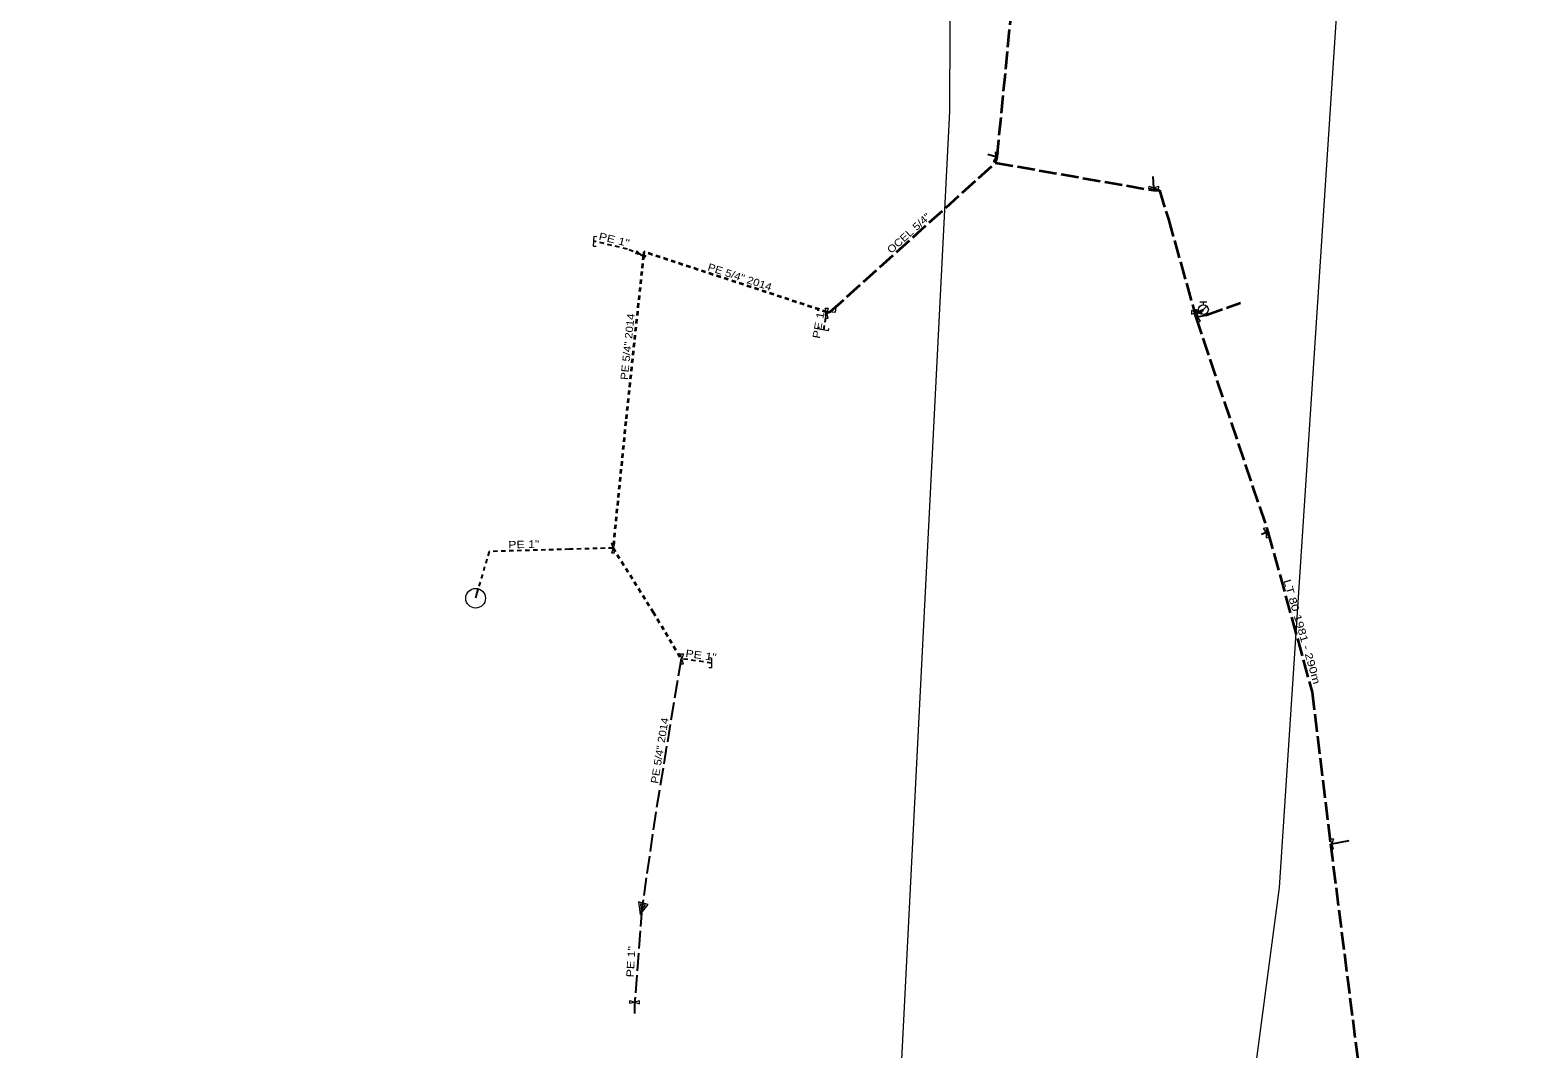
# Model space of a CAD drawing. Extents: x -616592 to -615844, y -1088988 to -1088174.
# Drawn here: x -616410.7 to -616257.7, y -1088838.7 to -1088735.2 of the extents above; entities that cross this region are included whole.
import ezdxf
from ezdxf.enums import TextEntityAlignment as Align

# ---------------------------------------------------------------- set-up
doc = ezdxf.new("R2010")
doc.units = 0
doc.header["$LTSCALE"] = 0.3
doc.linetypes.add('LONG_DASHED', pattern=[7.5, 6, -1.5])
doc.linetypes.add('SHORT_DASHED', pattern=[2.7, 1.5, -1.2])
for name, color, linetype, lineweight in [('1', 7, 'Continuous', 13), ('10', 7, 'Continuous', 13), ('35', 7, 'LONG_DASHED', 35), ('36', 7, 'SHORT_DASHED', 35), ('50', 7, 'LONG_DASHED', 25), ('51', 7, 'SHORT_DASHED', 25)]:
    doc.layers.add(name, color=color, linetype=linetype, lineweight=lineweight)
doc.layers.add('16', color=7, linetype='Continuous')
doc.layers.add('19', color=7, linetype='Continuous')

msp = doc.modelspace()

# ---------------------------------------------------------------- linework, layer by layer
at = {"layer": '1'}
msp.add_lwpolyline([(-616257.711, -1088587.328), (-616274.902, -1088683.788), (-616283.975, -1088822.271), (-616298.779, -1088934.012), (-616386.643, -1088972.214), (-616585.294, -1088987.972), (-616591.502, -1088951.68), (-616447.289, -1088935.922), (-616360.379, -1088913.001), (-616322.655, -1088847.102), (-616317.402, -1088743.479), (-616316.925, -1088623.142)], dxfattribs=at)
at = {"layer": '10'}
for p, q in [((-616353.562, -1088757.158), (-616353.492, -1088756.16)), ((-616353.562, -1088757.158), (-616353.313, -1088757.175)), ((-616353.492, -1088756.16), (-616353.242, -1088756.178)), ((-616292.01, -1088763.972), (-616291.303, -1088763.265)), ((-616292.006, -1088762.818), (-616291.306, -1088762.818)), ((-616291.656, -1088763.118), (-616291.656, -1088762.818)), ((-616330.004, -1088763.759), (-616330.065, -1088764.256)), ((-616292.364, -1088763.64), (-616292.614, -1088763.64)), ((-616330.69, -1088765.609), (-616330.652, -1088765.361)), ((-616329.702, -1088765.761), (-616330.69, -1088765.609)), ((-616329.702, -1088765.761), (-616329.664, -1088765.514)), ((-616341.594, -1088798.991), (-616341.844, -1088798.991)), ((-616341.594, -1088799.991), (-616341.844, -1088799.991)), ((-616341.594, -1088798.991), (-616341.594, -1088799.991))]:
    msp.add_line(p, q, dxfattribs=at)
for points in [[(-616312.722, -1088748.117), (-616312.747, -1088747.596), (-616312.456, -1088747.668), (-616312.722, -1088748.117), (-616312.988, -1088748.566), (-616312.697, -1088748.638)], [(-616296.689, -1088751.248), (-616297.198, -1088751.366), (-616297.178, -1088751.066), (-616296.689, -1088751.248), (-616296.2, -1088751.43), (-616296.18, -1088751.13)], [(-616348.785, -1088758.011), (-616348.271, -1088758.104), (-616348.408, -1088758.372), (-616348.785, -1088758.011), (-616349.162, -1088757.65), (-616349.299, -1088757.918)], [(-616329.891, -1088763.966), (-616330.041, -1088763.466), (-616329.741, -1088763.466), (-616329.891, -1088763.966), (-616330.041, -1088764.466), (-616329.741, -1088764.466)], [(-616292.252, -1088764.351), (-616292.535, -1088763.912), (-616292.247, -1088763.829), (-616292.252, -1088764.351), (-616292.257, -1088764.873), (-616291.969, -1088764.79)], [(-616285.279, -1088786.254), (-616285.561, -1088785.815), (-616285.273, -1088785.732), (-616285.279, -1088786.254), (-616285.285, -1088786.776), (-616284.997, -1088786.693)], [(-616351.581, -1088787.82), (-616351.731, -1088787.32), (-616351.431, -1088787.32), (-616351.581, -1088787.82), (-616351.731, -1088788.32), (-616351.431, -1088788.32)], [(-616344.584, -1088799.062), (-616344.734, -1088798.562), (-616344.434, -1088798.562), (-616344.584, -1088799.062), (-616344.734, -1088799.562), (-616344.434, -1088799.562)], [(-616278.619, -1088817.842), (-616278.769, -1088817.342), (-616278.469, -1088817.342), (-616278.619, -1088817.842), (-616278.769, -1088818.342), (-616278.469, -1088818.342)], [(-616348.022, -1088823.996), (-616348.986, -1088823.73), (-616348.824, -1088825.019)], [(-616348.279, -1088824.08), (-616348.809, -1088823.934), (-616348.72, -1088824.643)], [(-616349.389, -1088833.915), (-616349.894, -1088834.047), (-616349.883, -1088833.747), (-616349.389, -1088833.915), (-616348.895, -1088834.083), (-616348.884, -1088833.783)]]:
    msp.add_lwpolyline(points, close=True, dxfattribs=at)
for points in [[(-616330.004, -1088763.759), (-616329.012, -1088763.881), (-616328.951, -1088763.384)], [(-616292.364, -1088763.89), (-616291.864, -1088763.703), (-616291.864, -1088764.077), (-616292.364, -1088763.89), (-616292.864, -1088763.703), (-616292.864, -1088764.077), (-616292.364, -1088763.89), (-616292.364, -1088763.64), (-616292.114, -1088763.64)]]:
    msp.add_lwpolyline(points, dxfattribs=at)
for centre, radius in [((-616291.6558, -1088763.6177), 0.5), ((-616365.53, -1088792.911), 1)]:
    msp.add_circle(centre, radius, dxfattribs=at)
at = {"layer": '35'}
for p, q in [((-616312.591, -1088748.152), (-616309.946, -1088720.987)), ((-616312.762, -1088748.71), (-616312.591, -1088748.152)), ((-616291.426, -1088764.174), (-616287.885, -1088762.94)), ((-616292.547, -1088763.922), (-616292.364, -1088763.89)), ((-616292.547, -1088763.922), (-616292.439, -1088764.395)), ((-616292.439, -1088764.395), (-616285.108, -1088786.166)), ((-616292.364, -1088763.89), (-616291.656, -1088763.618))]:
    msp.add_line(p, q, dxfattribs=at)
for points in [[(-616329.508, -1088763.82), (-616312.762, -1088748.71), (-616296.736, -1088751.503)], [(-616296.736, -1088751.503), (-616296.129, -1088751.485), (-616295.213, -1088754.441), (-616292.547, -1088763.922)], [(-616285.108, -1088786.166), (-616280.628, -1088802.442), (-616278.755, -1088817.853)], [(-616278.755, -1088817.853), (-616274.722, -1088849.757), (-616273.259, -1088861.334)]]:
    msp.add_lwpolyline(points, dxfattribs=at)
at = {"layer": '36'}
for points in [[(-616348.504, -1088758.139), (-616350.291, -1088774.98), (-616351.581, -1088787.82)], [(-616329.88, -1088763.867), (-616348.462, -1088757.745), (-616348.504, -1088758.139)], [(-616329.88, -1088763.867), (-616329.685, -1088763.879), (-616329.508, -1088763.82)], [(-616351.581, -1088787.82), (-616347.51, -1088794.316), (-616344.684, -1088799.058)]]:
    msp.add_lwpolyline(points, dxfattribs=at)
at = {"layer": '50'}
for p, q in [((-616296.689, -1088751.248), (-616296.76, -1088750.099)), ((-616296.736, -1088751.503), (-616296.689, -1088751.248)), ((-616285.279, -1088786.254), (-616285.769, -1088786.444)), ((-616285.108, -1088786.166), (-616285.279, -1088786.254)), ((-616349.389, -1088833.915), (-616349.4, -1088835.084))]:
    msp.add_line(p, q, dxfattribs=at)
for points in [[(-616312.591, -1088748.152), (-616312.722, -1088748.117), (-616313.534, -1088747.852)], [(-616292.439, -1088764.395), (-616292.252, -1088764.351), (-616291.426, -1088764.174)], [(-616344.684, -1088799.058), (-616347.24, -1088814.627), (-616348.664, -1088824.441), (-616349.389, -1088833.915)], [(-616278.755, -1088817.853), (-616278.619, -1088817.842), (-616276.512, -1088817.453)]]:
    msp.add_lwpolyline(points, dxfattribs=at)
at = {"layer": '51'}
for p, q in [((-616348.785, -1088758.011), (-616348.504, -1088758.139)), ((-616344.584, -1088799.062), (-616344.684, -1088799.058)), ((-616341.594, -1088799.491), (-616344.584, -1088799.062))]:
    msp.add_line(p, q, dxfattribs=at)
for points in [[(-616348.785, -1088758.011), (-616350.13, -1088757.472), (-616353.527, -1088756.659)], [(-616330.196, -1088765.685), (-616329.891, -1088763.966), (-616329.88, -1088763.867)], [(-616351.581, -1088787.82), (-616356.017, -1088787.94), (-616364.146, -1088788.165), (-616365.456, -1088792.5), (-616365.53, -1088792.911)]]:
    msp.add_lwpolyline(points, dxfattribs=at)

# ---------------------------------------------------------------- texts
at = {"layer": '16'}
for s, rotation, width, p in [('OCEL 5/4"', 41.977, 1.15, (-616321.3158, -1088756.1332)), ('PE 5/4" 2014', 341.765, 1.15, (-616338.8358, -1088760.6539)), ('PE 5/4" 2014', 83.943, 1.15, (-616349.7388, -1088767.4121)), ('LT 80 1981 - 290m', 286.127, 1.3, (-616282.0033, -1088796.4113)), ('PE 5/4" 2014', 80.677, 1.15, (-616346.4768, -1088808.4353))]:
    msp.add_text(s, height=0.75, rotation=rotation, dxfattribs=dict(at, width=width)).set_placement(p, align=Align.CENTER)
at = {"layer": '19', "width": 1.25}
for s, rotation, p in [('PE 1" ', 346.541, (-616351.3818, -1088756.9151)), ('PE 1" ', 79.939, (-616330.3049, -1088764.869)), ('PE 1" ', 1.585, (-616360.4569, -1088787.8135)), ('PE 1" ', 351.835, (-616342.5348, -1088799.1032)), ('PE 1"', 86.695, (-616349.4042, -1088829.8386))]:
    msp.add_text(s, height=0.75, rotation=rotation, dxfattribs=at).set_placement(p, align=Align.CENTER)

doc.saveas('drawing.dxf')
